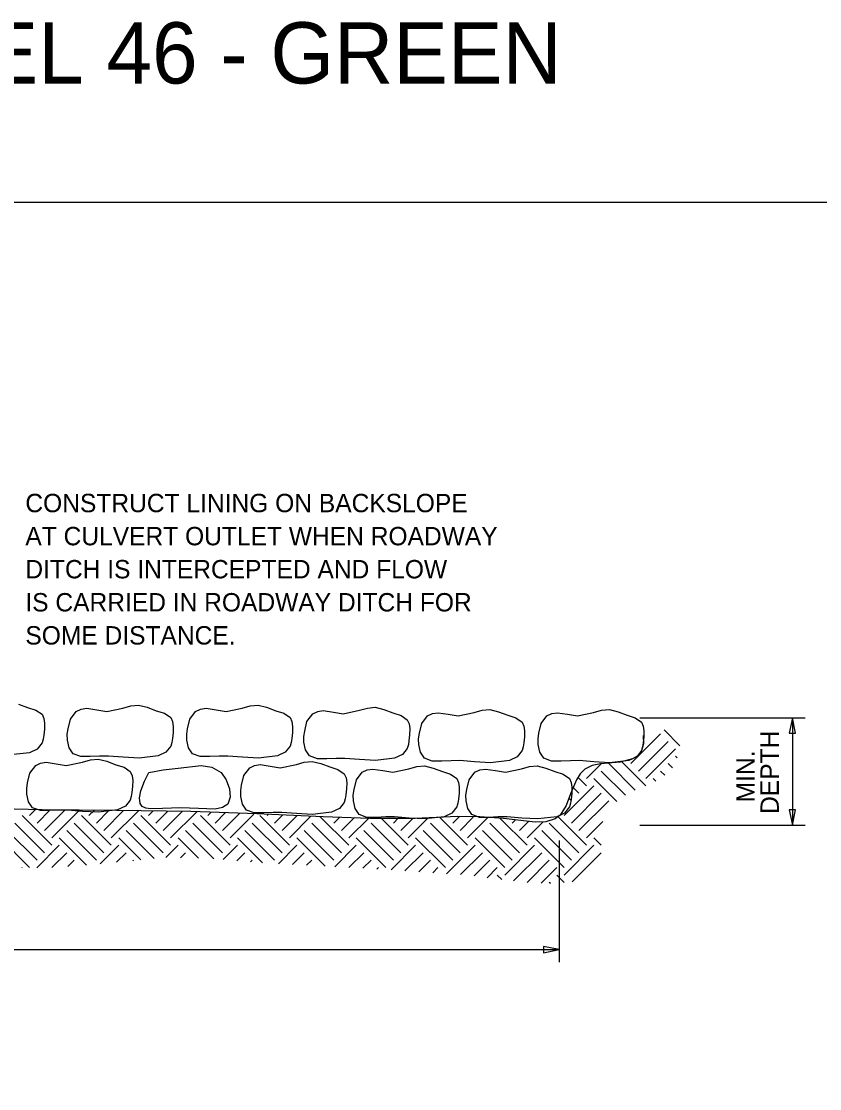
# Model space of a CAD drawing. Extents: x -439.1 to -407.9, y -458.1 to -436.2.
# Drawn here: x -424.91 to -418.4, y -444.91 to -436.2 of the extents above; entities that cross this region are included whole.
import ezdxf

# ---------------------------------------------------------------- set-up
doc = ezdxf.new("R2010")
doc.units = 0
for name, color, linetype in [('Draft_Named_Boundary', 7, 'Continuous'), ('Level 4', 7, 'Continuous'), ('Level 46', 7, 'Continuous')]:
    doc.layers.add(name, color=color, linetype=linetype)

msp = doc.modelspace()

# ---------------------------------------------------------------- linework, layer by layer
at = {"layer": 'Draft_Named_Boundary'}
msp.add_lwpolyline([(-439.109, -458.0508), (-407.859, -458.0508), (-407.859, -437.6758), (-439.109, -437.6758)], close=True, dxfattribs=at)
at = {"layer": 'Level 4'}
for p, q in [((-419.8623, -441.881), (-418.5146, -441.881)), ((-418.6174, -441.881), (-418.6174, -442.7589)), ((-419.9358, -442.2561), (-419.6934, -442.0136)), ((-419.5358, -442.1106), (-419.6659, -441.9805)), ((-419.8752, -442.3167), (-419.6328, -442.0742)), ((-419.8146, -442.3773), (-419.5722, -442.1348)), ((-419.5574, -442.2102), (-419.5722, -442.1955)), ((-420.2995, -442.3773), (-420.1803, -442.258)), ((-419.9006, -442.4732), (-420.1177, -442.2561)), ((-419.8146, -442.4379), (-420.0126, -442.2399)), ((-419.5972, -442.2917), (-419.6328, -442.2561)), ((-420.2995, -442.4379), (-420.3673, -442.3702)), ((-420.0518, -442.5644), (-420.2389, -442.3773)), ((-419.9803, -442.5147), (-420.1783, -442.3167)), ((-419.7314, -442.3999), (-419.754, -442.3773)), ((-419.6589, -442.3511), (-419.6934, -442.3167)), ((-420.4814, -442.6804), (-420.2389, -442.4379)), ((-420.3601, -442.4985), (-420.4072, -442.4515)), ((-420.4208, -442.5591), (-420.442, -442.5379)), ((-420.4208, -442.741), (-420.1783, -442.4985)), ((-420.3601, -442.8016), (-420.1177, -442.5591)), ((-424.8456, -442.6804), (-424.7969, -442.6317)), ((-424.785, -442.741), (-424.6776, -442.6336)), ((-424.7244, -442.8016), (-424.5582, -442.6354)), ((-424.6637, -442.8622), (-424.4383, -442.6367)), ((-424.3607, -442.6804), (-424.3181, -442.6378)), ((-424.3001, -442.741), (-424.1978, -442.6387)), ((-424.2394, -442.8016), (-424.0775, -442.6396)), ((-424.1788, -442.8622), (-423.9573, -442.6407)), ((-423.8758, -442.6804), (-423.8373, -442.6419)), ((-423.8151, -442.741), (-423.7176, -442.6435)), ((-423.7545, -442.8016), (-423.5986, -442.6457)), ((-423.6939, -442.8622), (-423.4807, -442.649)), ((-423.3908, -442.6804), (-423.3641, -442.6537)), ((-424.7244, -442.9834), (-424.9668, -442.741)), ((-424.6637, -442.9228), (-424.9062, -442.6804)), ((-424.2394, -442.9834), (-424.4819, -442.741)), ((-424.1788, -442.9228), (-424.4213, -442.6804)), ((-423.7545, -442.9834), (-423.997, -442.741)), ((-423.6939, -442.9228), (-423.9364, -442.6804)), ((-423.2696, -442.9834), (-423.5121, -442.741)), ((-423.209, -442.9228), (-423.4515, -442.6804)), ((-423.3302, -442.741), (-423.2476, -442.6583)), ((-423.2696, -442.8016), (-423.131, -442.663)), ((-423.209, -442.8622), (-423.0144, -442.6676)), ((-422.7847, -442.9834), (-423.0272, -442.741)), ((-422.7241, -442.9228), (-422.9665, -442.6804)), ((-422.9059, -442.6804), (-422.8979, -442.6723)), ((-422.8453, -442.741), (-422.7813, -442.677)), ((-422.7847, -442.8016), (-422.6647, -442.6816)), ((-422.7241, -442.8622), (-422.5482, -442.6863)), ((-422.2998, -442.9834), (-422.5422, -442.741)), ((-422.2392, -442.9228), (-422.4727, -442.6893)), ((-422.3604, -442.741), (-422.3123, -442.6929)), ((-422.2998, -442.8016), (-422.1934, -442.6952)), ((-422.2392, -442.8622), (-422.0744, -442.6975)), ((-421.8149, -442.9834), (-422.0573, -442.741)), ((-421.7543, -442.9228), (-421.9778, -442.6993)), ((-421.8755, -442.741), (-421.8366, -442.702)), ((-421.8149, -442.8016), (-421.7176, -442.7043)), ((-421.7543, -442.8622), (-421.5919, -442.6999)), ((-421.33, -442.9834), (-421.5724, -442.741)), ((-421.2694, -442.9228), (-421.4966, -442.6955)), ((-421.3906, -442.741), (-421.339, -442.6894)), ((-421.33, -442.8016), (-421.2227, -442.6943)), ((-421.2694, -442.8622), (-421.1064, -442.6992)), ((-420.8451, -442.9834), (-421.0875, -442.741)), ((-420.7844, -442.9228), (-421.0037, -442.7036)), ((-420.9057, -442.741), (-420.8822, -442.7176)), ((-420.8451, -442.8016), (-420.7725, -442.7291)), ((-420.7844, -442.8622), (-420.6534, -442.7312)), ((-420.3601, -442.9834), (-420.6026, -442.741)), ((-420.2995, -442.9228), (-420.5367, -442.6856)), ((-420.2995, -442.8622), (-420.1665, -442.7292)), ((-424.785, -443.044), (-425.0274, -442.8016)), ((-424.3001, -443.044), (-424.5425, -442.8016)), ((-423.8278, -443.0314), (-424.0576, -442.8016)), ((-423.3421, -443.0322), (-423.5727, -442.8016)), ((-422.8453, -443.044), (-423.0878, -442.8016)), ((-422.3604, -443.044), (-422.6029, -442.8016)), ((-421.8755, -443.044), (-422.118, -442.8016)), ((-421.3906, -443.044), (-421.633, -442.8016)), ((-420.9057, -443.044), (-421.1481, -442.8016)), ((-420.4208, -443.044), (-420.6632, -442.8016)), ((-419.8623, -442.7589), (-418.5146, -442.7589)), ((-424.8456, -443.1047), (-425.088, -442.8622)), ((-424.381, -443.0843), (-424.6031, -442.8622)), ((-423.9382, -443.0422), (-424.1182, -442.8622)), ((-423.4666, -443.0289), (-423.6333, -442.8622)), ((-422.9447, -443.0659), (-423.1484, -442.8622)), ((-422.4317, -443.094), (-422.6635, -442.8622)), ((-421.9361, -443.1047), (-422.1786, -442.8622)), ((-421.4512, -443.1047), (-421.6937, -442.8622)), ((-420.9663, -443.1047), (-421.2087, -442.8622)), ((-420.4814, -443.1047), (-420.7238, -442.8622)), ((-420.5223, -442.8845), (-420.5223, -443.8773)), ((-420.1793, -442.9218), (-420.2389, -442.8622)), ((-424.787, -443.1067), (-424.6031, -442.9228)), ((-424.6644, -443.1053), (-424.5425, -442.9834)), ((-424.27, -443.0746), (-424.1182, -442.9228)), ((-424.1356, -443.0615), (-424.0576, -442.9834)), ((-423.7326, -443.0221), (-423.6333, -442.9228)), ((-423.6144, -443.0251), (-423.5727, -442.9834)), ((-423.2644, -443.0388), (-423.1484, -442.9228)), ((-423.1527, -443.0483), (-423.0878, -442.9834)), ((-422.8137, -443.073), (-422.6635, -442.9228)), ((-422.6988, -443.0793), (-422.6029, -442.9834)), ((-422.354, -443.0982), (-422.1786, -442.9228)), ((-422.239, -443.1045), (-422.118, -442.9834)), ((-421.8943, -443.1235), (-421.6937, -442.9228)), ((-421.7808, -443.1312), (-421.633, -442.9834)), ((-421.4404, -443.1544), (-421.2087, -442.9228)), ((-421.3269, -443.1622), (-421.1481, -442.9834)), ((-420.9663, -443.1653), (-420.7238, -442.9228)), ((-420.8937, -443.2139), (-420.6632, -442.9834)), ((-420.4814, -443.1653), (-420.2389, -442.9228)), ((-420.4152, -443.2203), (-420.1794, -442.9846)), ((-424.5341, -443.0963), (-424.4819, -443.044)), ((-424.0013, -443.0484), (-423.997, -443.044)), ((-423.041, -443.0579), (-423.0272, -443.044)), ((-422.5838, -443.0856), (-422.5422, -443.044)), ((-422.1241, -443.1108), (-422.0573, -443.044)), ((-421.6673, -443.139), (-421.5724, -443.044)), ((-421.2164, -443.1729), (-421.0875, -443.044)), ((-420.784, -443.2255), (-420.6026, -443.044)), ((-424.9095, -443.108), (-424.9062, -443.1047)), ((-422.0092, -443.1171), (-421.9967, -443.1047)), ((-421.5539, -443.1467), (-421.5118, -443.1047)), ((-421.1094, -443.1872), (-421.0269, -443.1047)), ((-420.9897, -443.2024), (-421.0269, -443.1653)), ((-420.669, -443.2317), (-420.542, -443.1047)), ((-420.4808, -443.2265), (-420.542, -443.1653)), ((-420.5926, -443.2358), (-420.6026, -443.2259)), ((-431.8697, -443.7744), (-420.5223, -443.7744))]:
    msp.add_line(p, q, dxfattribs=at)
for points in [[(-424.9358, -441.7699), (-424.8618, -441.7979), (-424.7947, -441.8187), (-424.7435, -441.8537), (-424.7291, -441.8873), (-424.7238, -441.926), (-424.7248, -441.9756), (-424.7304, -442.0246), (-424.7352, -442.0568), (-424.7435, -442.087), (-424.7835, -442.1369), (-424.8469, -442.167), (-425.0031, -442.1856)], [(-419.8368, -442.0266), (-419.8337, -442.094), (-419.8513, -442.1565), (-419.8809, -442.1912), (-419.9222, -442.2159), (-420.0244, -442.243), (-420.1832, -442.2583), (-420.2536, -442.2719), (-420.313, -442.3007), (-420.3503, -442.3385), (-420.3806, -442.3873), (-420.4284, -442.5027), (-420.4657, -442.599), (-420.5149, -442.6759), (-420.555, -442.7059), (-420.6294, -442.7301), (-420.7167, -442.735), (-420.9766, -442.7047), (-421.1704, -442.6892), (-421.3513, -442.6889), (-421.698, -442.7047), (-422.069, -442.705), (-422.4482, -442.6903), (-422.9911, -442.6655), (-423.5303, -442.647), (-424.1356, -442.6392), (-424.7422, -442.6326), (-425.1968, -442.622)]]:
    msp.add_lwpolyline(points, dxfattribs=at)
for points in [[(-424.5304, -441.9717), (-424.512, -441.8931), (-424.4647, -441.8304), (-424.4243, -441.8109), (-424.3792, -441.8041), (-424.2964, -441.8165), (-424.2149, -441.8304), (-424.0836, -441.8025), (-424.0186, -441.7837), (-423.9553, -441.7779), (-423.8848, -441.7959), (-423.8108, -441.8239), (-423.7436, -441.8447), (-423.6925, -441.8797), (-423.6781, -441.9133), (-423.6728, -441.952), (-423.6738, -442.0016), (-423.6793, -442.0506), (-423.6841, -442.0828), (-423.6925, -442.113), (-423.7324, -442.1629), (-423.7959, -442.193), (-423.9521, -442.2116), (-424.082, -442.2044), (-424.2018, -442.1952), (-424.2735, -442.1953), (-424.3497, -442.1984), (-424.4268, -442.1984), (-424.4909, -442.1754), (-424.5232, -442.1265), (-424.5369, -442.0637), (-424.5377, -442.0168), (-424.5304, -441.9717)], [(-423.5558, -441.9717), (-423.5374, -441.8931), (-423.49, -441.8304), (-423.4497, -441.8109), (-423.4046, -441.8041), (-423.3218, -441.8165), (-423.2403, -441.8304), (-423.109, -441.8025), (-423.044, -441.7837), (-422.9807, -441.7779), (-422.9101, -441.7959), (-422.8362, -441.8239), (-422.769, -441.8447), (-422.7179, -441.8797), (-422.7035, -441.9133), (-422.6982, -441.952), (-422.6992, -442.0016), (-422.7047, -442.0506), (-422.7095, -442.0828), (-422.7179, -442.113), (-422.7578, -442.1629), (-422.8213, -442.193), (-422.9775, -442.2116), (-423.1074, -442.2044), (-423.2272, -442.1952), (-423.2989, -442.1953), (-423.375, -442.1984), (-423.4521, -442.1984), (-423.5163, -442.1754), (-423.5486, -442.1265), (-423.5623, -442.0637), (-423.5631, -442.0168), (-423.5558, -441.9717)], [(-422.5995, -441.9901), (-422.5812, -441.9115), (-422.5338, -441.8488), (-422.4934, -441.8293), (-422.4484, -441.8225), (-422.3656, -441.8349), (-422.2841, -441.8488), (-422.1528, -441.8209), (-422.0878, -441.8021), (-422.0245, -441.7962), (-421.9539, -441.8143), (-421.8799, -441.8423), (-421.8128, -441.8631), (-421.7616, -441.8981), (-421.7473, -441.9317), (-421.7419, -441.9704), (-421.7429, -442.02), (-421.7485, -442.069), (-421.7533, -442.1012), (-421.7616, -442.1314), (-421.8016, -442.1813), (-421.865, -442.2114), (-422.0212, -442.23), (-422.1512, -442.2228), (-422.271, -442.2135), (-422.3427, -442.2136), (-422.4188, -442.2168), (-422.4959, -442.2168), (-422.5601, -442.1938), (-422.5923, -442.1449), (-422.6061, -442.0821), (-422.6069, -442.0352), (-422.5995, -441.9901)], [(-421.6617, -442.0085), (-421.6433, -441.9299), (-421.596, -441.8672), (-421.5556, -441.8477), (-421.5106, -441.8409), (-421.4278, -441.8533), (-421.3463, -441.8672), (-421.215, -441.8393), (-421.15, -441.8205), (-421.0867, -441.8146), (-421.0161, -441.8327), (-420.9421, -441.8606), (-420.875, -441.8815), (-420.8238, -441.9165), (-420.8094, -441.9501), (-420.8041, -441.9888), (-420.8051, -442.0384), (-420.8107, -442.0874), (-420.8154, -442.1196), (-420.8238, -442.1498), (-420.8637, -442.1997), (-420.9272, -442.2297), (-421.0834, -442.2484), (-421.2134, -442.2411), (-421.3331, -442.2319), (-421.4048, -442.232), (-421.481, -442.2352), (-421.5581, -442.2352), (-421.6223, -442.2122), (-421.6545, -442.1633), (-421.6683, -442.1005), (-421.6691, -442.0536), (-421.6617, -442.0085)], [(-420.6871, -442.0085), (-420.6687, -441.9299), (-420.6214, -441.8672), (-420.581, -441.8477), (-420.536, -441.8409), (-420.4532, -441.8533), (-420.3717, -441.8672), (-420.2404, -441.8393), (-420.1754, -441.8205), (-420.1121, -441.8146), (-420.0415, -441.8327), (-419.9675, -441.8606), (-419.9004, -441.8815), (-419.8492, -441.9165), (-419.8348, -441.9501), (-419.8295, -441.9888), (-419.8305, -442.0384), (-419.8361, -442.0874), (-419.8408, -442.1196), (-419.8492, -442.1498), (-419.8891, -442.1997), (-419.9526, -442.2297), (-420.1088, -442.2484), (-420.2388, -442.2411), (-420.3585, -442.2319), (-420.4302, -442.232), (-420.5064, -442.2352), (-420.5835, -442.2352), (-420.6477, -442.2122), (-420.6799, -442.1633), (-420.6937, -442.1005), (-420.6945, -442.0536), (-420.6871, -442.0085)], [(-418.5912, -442.0074), (-418.6174, -441.881), (-418.6437, -442.0074)], [(-424.8614, -442.4131), (-424.843, -442.3344), (-424.7957, -442.2718), (-424.7553, -442.2522), (-424.7102, -442.2455), (-424.6274, -442.2578), (-424.5459, -442.2718), (-424.4146, -442.2439), (-424.3496, -442.225), (-424.2863, -442.2192), (-424.2158, -442.2372), (-424.1418, -442.2652), (-424.0746, -442.2861), (-424.0235, -442.321), (-424.0091, -442.3547), (-424.0038, -442.3933), (-424.0048, -442.4429), (-424.0103, -442.4919), (-424.0151, -442.5241), (-424.0235, -442.5543), (-424.0634, -442.6042), (-424.1269, -442.6343), (-424.2831, -442.6529), (-424.413, -442.6457), (-424.5328, -442.6365), (-424.6045, -442.6366), (-424.6807, -442.6398), (-424.7578, -442.6398), (-424.8219, -442.6168), (-424.8542, -442.5678), (-424.8679, -442.5051), (-424.8687, -442.4581), (-424.8614, -442.4131)], [(-423.8711, -442.3289), (-423.754, -442.3074), (-423.632, -442.2922), (-423.4438, -442.2711), (-423.3565, -442.2837), (-423.2826, -442.3289), (-423.2402, -442.3887), (-423.2138, -442.4606), (-423.2079, -442.5309), (-423.2275, -442.5864), (-423.2698, -442.6154), (-423.3293, -442.6269), (-423.4665, -442.6232), (-423.6131, -442.6179), (-423.7607, -442.6232), (-423.8546, -442.6262), (-423.8956, -442.6203), (-423.9262, -442.6048), (-423.9414, -442.5823), (-423.9473, -442.5355), (-423.9374, -442.4786), (-423.9081, -442.3989), (-423.8711, -442.3289)], [(-423.1144, -442.4314), (-423.0961, -442.3528), (-423.0487, -442.2902), (-423.0083, -442.2706), (-422.9633, -442.2639), (-422.8805, -442.2762), (-422.799, -442.2902), (-422.6677, -442.2622), (-422.6027, -442.2434), (-422.5394, -442.2376), (-422.4688, -442.2556), (-422.3948, -442.2836), (-422.3277, -442.3045), (-422.2765, -442.3394), (-422.2621, -442.3731), (-422.2568, -442.4117), (-422.2578, -442.4613), (-422.2634, -442.5103), (-422.2682, -442.5425), (-422.2765, -442.5727), (-422.3165, -442.6226), (-422.3799, -442.6527), (-422.5361, -442.6713), (-422.6661, -442.6641), (-422.7858, -442.6549), (-422.8576, -442.655), (-422.9337, -442.6582), (-423.0108, -442.6582), (-423.075, -442.6352), (-423.1072, -442.5862), (-423.121, -442.5235), (-423.1218, -442.4765), (-423.1144, -442.4314)], [(-422.195, -442.4682), (-422.1766, -442.3896), (-422.1293, -442.3269), (-422.0889, -442.3074), (-422.0438, -442.3006), (-421.961, -442.313), (-421.8795, -442.3269), (-421.7482, -442.299), (-421.6833, -442.2802), (-421.62, -442.2744), (-421.5494, -442.2924), (-421.4754, -442.3204), (-421.4083, -442.3412), (-421.3571, -442.3762), (-421.3427, -442.4098), (-421.3374, -442.4485), (-421.3384, -442.4981), (-421.3439, -442.5471), (-421.3487, -442.5793), (-421.3571, -442.6095), (-421.397, -442.6594), (-421.4605, -442.6895), (-421.6167, -442.7081), (-421.7466, -442.7009), (-421.8664, -442.6917), (-421.9381, -442.6917), (-422.0143, -442.6949), (-422.0914, -442.6949), (-422.1556, -442.6719), (-422.1878, -442.623), (-422.2016, -442.5602), (-422.2024, -442.5133), (-422.195, -442.4682)], [(-421.2755, -442.4682), (-421.2572, -442.3896), (-421.2098, -442.3269), (-421.1694, -442.3074), (-421.1244, -442.3006), (-421.0416, -442.313), (-420.9601, -442.3269), (-420.8288, -442.299), (-420.7638, -442.2802), (-420.7005, -442.2744), (-420.6299, -442.2924), (-420.5559, -442.3204), (-420.4888, -442.3412), (-420.4376, -442.3762), (-420.4233, -442.4098), (-420.4179, -442.4485), (-420.4189, -442.4981), (-420.4245, -442.5471), (-420.4293, -442.5793), (-420.4376, -442.6095), (-420.4776, -442.6594), (-420.541, -442.6895), (-420.6972, -442.7081), (-420.8272, -442.7009), (-420.947, -442.6917), (-421.0187, -442.6917), (-421.0948, -442.6949), (-421.1719, -442.6949), (-421.2361, -442.6719), (-421.2683, -442.623), (-421.2821, -442.5602), (-421.2829, -442.5133), (-421.2755, -442.4682)], [(-418.6437, -442.6324), (-418.6174, -442.7589), (-418.5912, -442.6324)], [(-420.6487, -443.8007), (-420.5223, -443.7744), (-420.6487, -443.7482)]]:
    msp.add_lwpolyline(points, close=True, dxfattribs=at)

# ---------------------------------------------------------------- texts
for s, p in [('CONSTRUCT LINING ON BACKSLOPE ', (-424.8801, -440.204)), ('AT CULVERT OUTLET WHEN ROADWAY ', (-424.8801, -440.474)), ('DITCH IS INTERCEPTED AND FLOW ', (-424.8801, -440.744)), ('IS CARRIED IN ROADWAY DITCH FOR ', (-424.8801, -441.014)), ('SOME DISTANCE.', (-424.8801, -441.284))]:
    msp.add_text(s, height=0.15, dxfattribs=at).set_placement(p)
for s, p in [('DEPTH', (-418.7284, -442.6668)), ('MIN.', (-418.9261, -442.5729))]:
    msp.add_text(s, height=0.15, rotation=90, dxfattribs=at).set_placement(p)
at = {"layer": 'Level 46'}
msp.add_text('METRIC - LEVEL 46 - GREEN', height=0.5, dxfattribs=at).set_placement((-429.6416, -436.7047))

doc.saveas('drawing.dxf')
